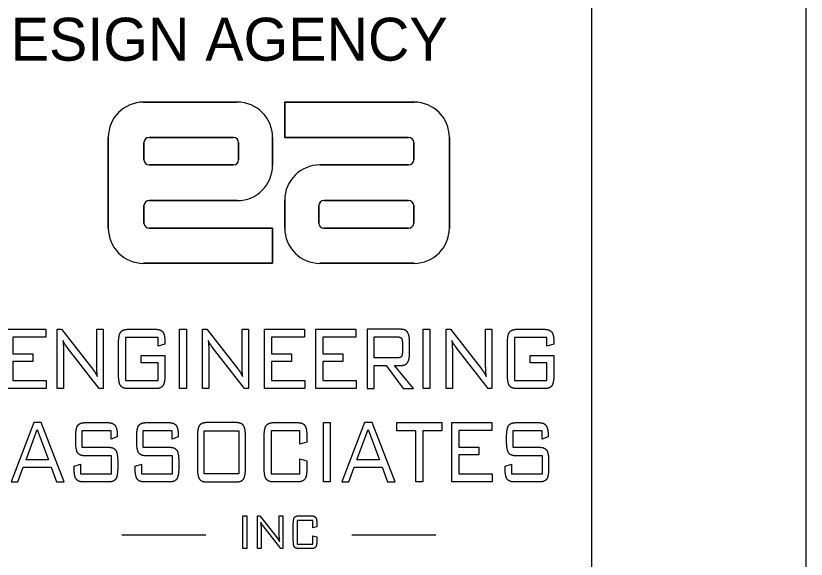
# Model space of a CAD drawing. Extents: x 0 to 34, y 0 to 22.
# Drawn here: x 32.158 to 34, y 3.688 to 4.955 of the extents above; entities that cross this region are included whole.
import ezdxf

# ---------------------------------------------------------------- set-up
doc = ezdxf.new("R2010")
doc.units = 0
for name, color, linetype in [('SH_Border', 7, 'Continuous'), ('SH_Cut_Line', 7, 'Continuous'), ('SH_Data', 7, 'Continuous'), ('TX_X_20', 7, 'Continuous')]:
    doc.layers.add(name, color=color, linetype=linetype)

msp = doc.modelspace()

# ---------------------------------------------------------------- linework, layer by layer
at = {"layer": 'SH_Border'}
msp.add_lwpolyline([(1.5, 21.5), (33.5, 21.5), (33.5, 0.5), (1.5, 0.5)], close=True, dxfattribs=at)
at = {"layer": 'SH_Cut_Line'}
msp.add_lwpolyline([(0, 0), (34, 0), (34, 22), (0, 22)], close=True, dxfattribs=at)
at = {"layer": 'SH_Data'}
msp.add_line((32.75, 4), (32.75, 4), dxfattribs=at)
at = {"layer": 'TX_X_20'}
for p, q in [((32.6745, 4.7533), (32.456, 4.7533)), ((32.456, 4.7533), (32.6745, 4.7533)), ((32.785, 4.7533), (33.0865, 4.7533)), ((32.785, 4.6713), (32.785, 4.7533)), ((32.3739, 4.6713), (32.3739, 4.4597)), ((32.3739, 4.4597), (32.3739, 4.6713)), ((32.457, 4.6189), (32.457, 4.6594)), ((32.457, 4.6594), (32.457, 4.6189)), ((32.4688, 4.6713), (32.6656, 4.6713)), ((32.6656, 4.6713), (32.4688, 4.6713)), ((32.6775, 4.6594), (32.6775, 4.6189)), ((32.6775, 4.6189), (32.6775, 4.6594)), ((32.7566, 4.606), (32.7566, 4.6713)), ((32.7566, 4.6713), (32.7566, 4.606)), ((33.0737, 4.6713), (32.785, 4.6713)), ((33.0855, 4.6594), (33.0855, 4.6189)), ((33.0855, 4.6189), (33.0855, 4.6594)), ((33.1686, 4.4597), (33.1686, 4.6713)), ((33.1686, 4.6713), (33.1686, 4.4597)), ((32.6656, 4.607), (32.4688, 4.607)), ((32.4688, 4.607), (32.6656, 4.607)), ((33.0737, 4.607), (32.8671, 4.607)), ((32.8671, 4.607), (33.0737, 4.607)), ((32.457, 4.4716), (32.457, 4.5121)), ((32.457, 4.5121), (32.457, 4.4716)), ((32.4688, 4.524), (32.6745, 4.524)), ((32.6745, 4.524), (32.4688, 4.524)), ((32.785, 4.525), (32.785, 4.4597)), ((32.785, 4.4597), (32.785, 4.525)), ((32.8641, 4.4716), (32.8641, 4.5121)), ((32.8641, 4.5121), (32.8641, 4.4716)), ((32.876, 4.524), (33.0737, 4.524)), ((33.0737, 4.524), (32.876, 4.524)), ((33.0855, 4.5121), (33.0855, 4.4716)), ((33.0855, 4.4716), (33.0855, 4.5121)), ((32.4688, 4.4597), (32.7566, 4.4597)), ((32.7566, 4.4597), (32.7566, 4.3777)), ((33.0737, 4.4597), (32.876, 4.4597)), ((32.876, 4.4597), (33.0737, 4.4597)), ((32.7566, 4.3777), (32.456, 4.3777)), ((32.8671, 4.3777), (33.0865, 4.3777)), ((33.0865, 4.3777), (32.8671, 4.3777)), ((32.4205, 4.224), (32.4832, 4.224)), ((33.3267, 4.224), (33.3893, 4.224)), ((32.3978, 4.1184), (32.3978, 4.1913)), ((33.0591, 4.1918), (33.0591, 4.1716)), ((33.0755, 4.1662), (33.0755, 4.1972)), ((33.3039, 4.1184), (33.3039, 4.1913)), ((32.4832, 4.0856), (32.4205, 4.0856)), ((33.3893, 4.0856), (33.3267, 4.0856)), ((32.3205, 4.0065), (32.3719, 4.0065)), ((32.4627, 4.0065), (32.5142, 4.0065)), ((32.6711, 4.0065), (32.6041, 4.0065)), ((32.7599, 4.0065), (32.814, 4.0065)), ((33.3246, 4.0065), (33.3761, 4.0065)), ((32.2979, 3.9618), (32.2979, 3.9738)), ((32.4401, 3.9618), (32.4401, 3.9738)), ((32.5814, 3.9738), (32.5814, 3.9009)), ((32.6936, 3.9009), (32.6936, 3.9738)), ((32.7371, 3.9009), (32.7371, 3.9738)), ((33.302, 3.9618), (33.302, 3.9738)), ((32.3958, 3.9164), (32.3958, 3.9009)), ((32.538, 3.9164), (32.538, 3.9009)), ((33.3999, 3.9164), (33.3999, 3.9009)), ((32.3733, 3.8681), (32.3169, 3.8681)), ((32.5155, 3.8681), (32.4591, 3.8681)), ((32.6041, 3.8681), (32.6711, 3.8681)), ((32.814, 3.8681), (32.7599, 3.8681)), ((33.3774, 3.8681), (33.321, 3.8681)), ((32.8175, 3.7891), (32.8473, 3.7891)), ((32.805, 3.7309), (32.805, 3.7711)), ((32.4056, 3.7451), (32.6008, 3.7451)), ((32.9416, 3.7451), (33.1369, 3.7451)), ((32.8473, 3.7129), (32.8175, 3.7129))]:
    msp.add_line(p, q, dxfattribs=at)
for points in [[(33.0865, 4.7533), (32.785, 4.7533), (32.785, 4.6713), (33.0737, 4.6713)], [(32.456, 4.3777), (32.7566, 4.3777), (32.7566, 4.4597), (32.4688, 4.4597)], [(32.2695, 4.1672), (32.2695, 4.0856), (32.2547, 4.0856), (32.2547, 4.224), (32.2649, 4.224), (32.3374, 4.1315)], [(32.3469, 4.1481), (32.3469, 4.224), (32.3617, 4.224), (32.3617, 4.0856), (32.3526, 4.0856), (32.2782, 4.1819)], [(32.608, 4.1672), (32.608, 4.0856), (32.5932, 4.0856), (32.5932, 4.224), (32.6034, 4.224), (32.6759, 4.1315)], [(32.6854, 4.1481), (32.6854, 4.224), (32.7002, 4.224), (32.7002, 4.0856), (32.6912, 4.0856), (32.6168, 4.1819)], [(33.055, 4.224), (32.9769, 4.224), (32.9769, 4.0856), (32.9932, 4.0856), (32.9932, 4.1395), (33.0217, 4.1395), (33.0611, 4.0856), (33.0851, 4.0856), (33.0408, 4.1395), (33.055, 4.1395)], [(33.1756, 4.1672), (33.1756, 4.0856), (33.1608, 4.0856), (33.1608, 4.224), (33.171, 4.224), (33.2435, 4.1315)], [(33.253, 4.1481), (33.253, 4.224), (33.2678, 4.224), (33.2678, 4.0856), (33.2588, 4.0856), (33.1844, 4.1819)], [(32.5059, 4.1929), (32.5059, 4.1895), (32.4898, 4.1849), (32.4898, 4.2052), (32.4139, 4.2052), (32.4139, 4.1049), (32.4898, 4.1049), (32.4898, 4.1456), (32.4506, 4.1456), (32.4506, 4.1632), (32.5059, 4.1632), (32.5059, 4.1184)], [(33.0487, 4.1574), (32.9932, 4.1574), (32.9932, 4.2062), (33.0487, 4.2062)], [(33.4121, 4.1929), (33.4121, 4.1895), (33.3959, 4.1849), (33.3959, 4.2052), (33.3201, 4.2052), (33.3201, 4.1049), (33.3959, 4.1049), (33.3959, 4.1456), (33.3567, 4.1456), (33.3567, 4.1632), (33.4121, 4.1632), (33.4121, 4.1184)], [(32.3947, 3.9762), (32.3947, 3.9733), (32.3808, 3.9676), (32.3808, 3.9877), (32.3124, 3.9877), (32.3124, 3.9491), (32.3733, 3.9491)], [(32.5369, 3.9762), (32.5369, 3.9733), (32.523, 3.9676), (32.523, 3.9877), (32.4546, 3.9877), (32.4546, 3.9491), (32.5155, 3.9491)], [(32.8366, 3.9738), (32.8366, 3.9608), (32.8204, 3.9565), (32.8204, 3.9877), (32.7533, 3.9877), (32.7533, 3.8874), (32.8204, 3.8874), (32.8204, 3.9221), (32.8366, 3.9172), (32.8366, 3.9009)], [(33.3988, 3.9762), (33.3988, 3.9733), (33.3849, 3.9676), (33.3849, 3.9877), (33.3165, 3.9877), (33.3165, 3.9491), (33.3774, 3.9491)], [(32.2942, 3.9009), (32.2942, 3.9047), (32.3092, 3.9096), (32.3092, 3.8874), (32.3813, 3.8874), (32.3813, 3.929), (32.3205, 3.929)], [(32.4364, 3.9009), (32.4364, 3.9047), (32.4514, 3.9096), (32.4514, 3.8874), (32.5235, 3.8874), (32.5235, 3.929), (32.4627, 3.929)], [(33.2983, 3.9009), (33.2983, 3.9047), (33.3133, 3.9096), (33.3133, 3.8874), (33.3854, 3.8874), (33.3854, 3.929), (33.3246, 3.929)], [(32.7298, 3.7578), (32.7298, 3.7129), (32.7216, 3.7129), (32.7216, 3.7891), (32.7272, 3.7891), (32.7671, 3.7381)], [(32.7723, 3.7473), (32.7723, 3.7891), (32.7805, 3.7891), (32.7805, 3.7129), (32.7755, 3.7129), (32.7345, 3.7659)], [(32.8597, 3.7711), (32.8597, 3.7639), (32.8507, 3.7615), (32.8507, 3.7787), (32.8139, 3.7787), (32.8139, 3.7235), (32.8507, 3.7235), (32.8507, 3.7426), (32.8597, 3.7399), (32.8597, 3.7309)]]:
    msp.add_lwpolyline(points, dxfattribs=at)
for points in [[(32.1351, 4.0856), (32.1351, 4.224), (32.2283, 4.224), (32.2283, 4.2055), (32.1513, 4.2055), (32.1513, 4.167), (32.1984, 4.167), (32.1984, 4.1487), (32.1513, 4.1487), (32.1513, 4.1046), (32.2291, 4.1046), (32.2291, 4.0856)], [(32.5396, 4.0856), (32.5396, 4.224), (32.5558, 4.224), (32.5558, 4.0856)], [(32.7376, 4.0856), (32.7376, 4.224), (32.8309, 4.224), (32.8309, 4.2055), (32.7539, 4.2055), (32.7539, 4.167), (32.801, 4.167), (32.801, 4.1487), (32.7539, 4.1487), (32.7539, 4.1046), (32.8316, 4.1046), (32.8316, 4.0856)], [(32.8573, 4.0856), (32.8573, 4.224), (32.9505, 4.224), (32.9505, 4.2055), (32.8735, 4.2055), (32.8735, 4.167), (32.9206, 4.167), (32.9206, 4.1487), (32.8735, 4.1487), (32.8735, 4.1046), (32.9513, 4.1046), (32.9513, 4.0856)], [(33.1072, 4.0856), (33.1072, 4.224), (33.1234, 4.224), (33.1234, 4.0856)], [(32.1472, 3.8681), (32.1631, 3.8681), (32.1755, 3.9023), (32.241, 3.9023), (32.2534, 3.8681), (32.2712, 3.8681), (32.2174, 4.0065), (32.2001, 4.0065)], [(32.875, 3.8681), (32.875, 4.0065), (32.8912, 4.0065), (32.8912, 3.8681)], [(32.9182, 3.8681), (32.9341, 3.8681), (32.9465, 3.9023), (33.012, 3.9023), (33.0244, 3.8681), (33.0422, 3.8681), (32.9884, 4.0065), (32.9711, 4.0065)], [(33.1068, 3.9877), (33.1068, 3.8681), (33.0907, 3.8681), (33.0907, 3.9877), (33.0464, 3.9877), (33.0464, 4.0065), (33.1513, 4.0065), (33.1513, 3.9877)], [(33.1742, 3.8681), (33.1742, 4.0065), (33.2675, 4.0065), (33.2675, 3.988), (33.1905, 3.988), (33.1905, 3.9495), (33.2376, 3.9495), (33.2376, 3.9312), (33.1905, 3.9312), (33.1905, 3.8871), (33.2682, 3.8871), (33.2682, 3.8681)], [(32.1823, 3.9199), (32.2083, 3.9907), (32.2344, 3.9199)], [(32.5975, 3.8874), (32.5975, 3.9877), (32.6777, 3.9877), (32.6777, 3.8874)], [(32.9533, 3.9199), (32.9793, 3.9907), (33.0054, 3.9199)], [(32.6874, 3.7129), (32.6874, 3.7891), (32.6964, 3.7891), (32.6964, 3.7129)]]:
    msp.add_lwpolyline(points, close=True, dxfattribs=at)
for centre, radius, start, end in [((32.456, 4.6713), 0.0821, 90, 180), ((32.456, 4.6713), 0.0821, 90, 180), ((32.6745, 4.6713), 0.0821, 0, 90), ((32.6745, 4.6713), 0.0821, 0, 90), ((33.0865, 4.6713), 0.0821, 0, 90), ((33.0865, 4.6713), 0.0821, 0, 90), ((32.4688, 4.6594), 0.0119, 90, 180), ((32.4688, 4.6594), 0.0119, 90, 180), ((32.6656, 4.6594), 0.0119, 0, 90), ((32.6656, 4.6594), 0.0119, 0, 90), ((33.0737, 4.6594), 0.0119, 0, 90), ((33.0737, 4.6594), 0.0119, 0, 90), ((32.4688, 4.6189), 0.0119, 180, 270), ((32.4688, 4.6189), 0.0119, 180, 270), ((32.6656, 4.6189), 0.0119, 270, 0), ((32.6656, 4.6189), 0.0119, 270, 0), ((32.6745, 4.606), 0.0821, 270, 360), ((32.6745, 4.606), 0.0821, 270, 360), ((32.8671, 4.525), 0.0821, 90, 180), ((32.8671, 4.525), 0.0821, 90, 180), ((33.0737, 4.6189), 0.0119, 270, 0), ((33.0737, 4.6189), 0.0119, 270, 0), ((32.4688, 4.5121), 0.0119, 90, 180), ((32.4688, 4.5121), 0.0119, 90, 180), ((32.876, 4.5121), 0.0119, 90, 180), ((32.876, 4.5121), 0.0119, 90, 180), ((33.0737, 4.5121), 0.0119, 0, 90), ((33.0737, 4.5121), 0.0119, 0, 90), ((32.456, 4.4597), 0.0821, 180, 270), ((32.456, 4.4597), 0.0821, 180, 270), ((32.4688, 4.4716), 0.0119, 180, 270), ((32.4688, 4.4716), 0.0119, 180, 270), ((32.8671, 4.4597), 0.0821, 180, 270), ((32.8671, 4.4597), 0.0821, 180, 270), ((32.876, 4.4716), 0.0119, 180, 270), ((32.876, 4.4716), 0.0119, 180, 270), ((33.0737, 4.4716), 0.0119, 270, 0), ((33.0737, 4.4716), 0.0119, 270, 0), ((33.0865, 4.4597), 0.0821, 270, 360), ((33.0865, 4.4597), 0.0821, 270, 360)]:
    msp.add_arc(centre, radius, start, end, dxfattribs=at)
for points in [[(32.4025, 4.2171), (32.4072, 4.224), (32.4205, 4.224)], [(32.4832, 4.224), (32.4962, 4.224), (32.5011, 4.2173)], [(33.0707, 4.2177), (33.0659, 4.224), (33.055, 4.224)], [(33.0755, 4.1972), (33.0755, 4.2113), (33.0707, 4.2177)], [(33.3086, 4.2171), (33.3134, 4.224), (33.3267, 4.224)], [(33.3893, 4.224), (33.4023, 4.224), (33.4072, 4.2173)], [(32.3978, 4.1913), (32.3978, 4.2102), (32.4025, 4.2171)], [(32.5011, 4.2173), (32.5059, 4.2105), (32.5059, 4.1929)], [(33.0487, 4.2062), (33.0546, 4.2062), (33.0569, 4.2029)], [(33.0569, 4.2029), (33.0591, 4.1997), (33.0591, 4.1918)], [(33.3039, 4.1913), (33.3039, 4.2102), (33.3086, 4.2171)], [(33.4072, 4.2173), (33.4121, 4.2105), (33.4121, 4.1929)], [(32.2766, 4.184), (32.2711, 4.191), (32.2684, 4.1975)], [(32.2684, 4.1975), (32.269, 4.1912), (32.2692, 4.184)], [(32.2692, 4.184), (32.2695, 4.1769), (32.2695, 4.1672)], [(32.2782, 4.1819), (32.2777, 4.1825), (32.2766, 4.184)], [(32.6151, 4.184), (32.6096, 4.191), (32.6069, 4.1975)], [(32.6069, 4.1975), (32.6075, 4.1912), (32.6078, 4.184)], [(32.6078, 4.184), (32.608, 4.1769), (32.608, 4.1672)], [(32.6168, 4.1819), (32.6162, 4.1825), (32.6151, 4.184)], [(33.1827, 4.184), (33.1772, 4.191), (33.1746, 4.1975)], [(33.1746, 4.1975), (33.1751, 4.1912), (33.1754, 4.184)], [(33.1754, 4.184), (33.1756, 4.1769), (33.1756, 4.1672)], [(33.1844, 4.1819), (33.1838, 4.1825), (33.1827, 4.184)], [(33.0591, 4.1716), (33.0591, 4.1637), (33.0569, 4.1606)], [(33.0707, 4.1459), (33.0755, 4.1522), (33.0755, 4.1662)], [(32.3473, 4.128), (32.3469, 4.1353), (32.3469, 4.1481)], [(32.6858, 4.128), (32.6854, 4.1353), (32.6854, 4.1481)], [(33.0569, 4.1606), (33.0547, 4.1574), (33.0487, 4.1574)], [(33.055, 4.1395), (33.0659, 4.1395), (33.0707, 4.1459)], [(33.2534, 4.128), (33.253, 4.1353), (33.253, 4.1481)], [(32.3374, 4.1315), (32.3398, 4.1283), (32.3426, 4.1239)], [(32.3484, 4.114), (32.3476, 4.1207), (32.3473, 4.128)], [(32.6759, 4.1315), (32.6784, 4.1283), (32.6812, 4.1239)], [(32.6869, 4.114), (32.6862, 4.1207), (32.6858, 4.128)], [(33.2435, 4.1315), (33.246, 4.1283), (33.2488, 4.1239)], [(33.2545, 4.114), (33.2538, 4.1207), (33.2534, 4.128)], [(32.3426, 4.1239), (32.3454, 4.1194), (32.3484, 4.114)], [(32.4025, 4.0926), (32.3978, 4.0995), (32.3978, 4.1184)], [(32.5059, 4.1184), (32.5059, 4.0994), (32.5012, 4.0925)], [(32.6812, 4.1239), (32.684, 4.1194), (32.6869, 4.114)], [(33.2488, 4.1239), (33.2516, 4.1194), (33.2545, 4.114)], [(33.3086, 4.0926), (33.3039, 4.0995), (33.3039, 4.1184)], [(33.4121, 4.1184), (33.4121, 4.0994), (33.4073, 4.0925)], [(32.4205, 4.0856), (32.4072, 4.0856), (32.4025, 4.0926)], [(32.5012, 4.0925), (32.4964, 4.0856), (32.4832, 4.0856)], [(33.3267, 4.0856), (33.3134, 4.0856), (33.3086, 4.0926)], [(33.4073, 4.0925), (33.4025, 4.0856), (33.3893, 4.0856)], [(32.2979, 3.9738), (32.2979, 3.9928), (32.3026, 3.9997)], [(32.3026, 3.9997), (32.3072, 4.0065), (32.3205, 4.0065)], [(32.3719, 4.0065), (32.3849, 4.0065), (32.3898, 3.9998)], [(32.3898, 3.9998), (32.3947, 3.9931), (32.3947, 3.9762)], [(32.4401, 3.9738), (32.4401, 3.9928), (32.4448, 3.9997)], [(32.4448, 3.9997), (32.4495, 4.0065), (32.4627, 4.0065)], [(32.5142, 4.0065), (32.5271, 4.0065), (32.532, 3.9998)], [(32.532, 3.9998), (32.5369, 3.9931), (32.5369, 3.9762)], [(32.5861, 3.9996), (32.5814, 3.9927), (32.5814, 3.9738)], [(32.6041, 4.0065), (32.5908, 4.0065), (32.5861, 3.9996)], [(32.6889, 3.9997), (32.6842, 4.0065), (32.6711, 4.0065)], [(32.6936, 3.9738), (32.6936, 3.9928), (32.6889, 3.9997)], [(32.7371, 3.9738), (32.7371, 3.9928), (32.7419, 3.9997)], [(32.7419, 3.9997), (32.7467, 4.0065), (32.7599, 4.0065)], [(32.814, 4.0065), (32.8272, 4.0065), (32.8319, 3.9997)], [(32.8319, 3.9997), (32.8366, 3.9929), (32.8366, 3.9738)], [(33.302, 3.9738), (33.302, 3.9928), (33.3067, 3.9997)], [(33.3067, 3.9997), (33.3114, 4.0065), (33.3246, 4.0065)], [(33.3761, 4.0065), (33.389, 4.0065), (33.3939, 3.9998)], [(33.3939, 3.9998), (33.3988, 3.9931), (33.3988, 3.9762)], [(32.3026, 3.9359), (32.2979, 3.9428), (32.2979, 3.9618)], [(32.4448, 3.9359), (32.4401, 3.9428), (32.4401, 3.9618)], [(33.3067, 3.9359), (33.302, 3.9428), (33.302, 3.9618)], [(32.3733, 3.9491), (32.3863, 3.9491), (32.391, 3.9423)], [(32.391, 3.9423), (32.3958, 3.9355), (32.3958, 3.9164)], [(32.5155, 3.9491), (32.5285, 3.9491), (32.5333, 3.9423)], [(32.5333, 3.9423), (32.538, 3.9355), (32.538, 3.9164)], [(33.3774, 3.9491), (33.3904, 3.9491), (33.3952, 3.9423)], [(33.3952, 3.9423), (33.3999, 3.9355), (33.3999, 3.9164)], [(32.3205, 3.929), (32.3072, 3.929), (32.3026, 3.9359)], [(32.4627, 3.929), (32.4495, 3.929), (32.4448, 3.9359)], [(33.3246, 3.929), (33.3114, 3.929), (33.3067, 3.9359)], [(32.2989, 3.875), (32.2942, 3.8819), (32.2942, 3.9009)], [(32.3958, 3.9009), (32.3958, 3.8818), (32.3911, 3.875)], [(32.4411, 3.875), (32.4364, 3.8819), (32.4364, 3.9009)], [(32.538, 3.9009), (32.538, 3.8818), (32.5333, 3.875)], [(32.5814, 3.9009), (32.5814, 3.882), (32.5861, 3.8751)], [(32.6889, 3.875), (32.6936, 3.8818), (32.6936, 3.9009)], [(32.7419, 3.875), (32.7371, 3.8819), (32.7371, 3.9009)], [(32.8366, 3.9009), (32.8366, 3.8818), (32.8319, 3.875)], [(33.3031, 3.875), (33.2983, 3.8819), (33.2983, 3.9009)], [(33.3999, 3.9009), (33.3999, 3.8818), (33.3953, 3.875)], [(32.3169, 3.8681), (32.3037, 3.8681), (32.2989, 3.875)], [(32.3911, 3.875), (32.3865, 3.8681), (32.3733, 3.8681)], [(32.4591, 3.8681), (32.4459, 3.8681), (32.4411, 3.875)], [(32.5333, 3.875), (32.5287, 3.8681), (32.5155, 3.8681)], [(32.5861, 3.8751), (32.5908, 3.8681), (32.6041, 3.8681)], [(32.6711, 3.8681), (32.6842, 3.8681), (32.6889, 3.875)], [(32.7599, 3.8681), (32.7467, 3.8681), (32.7419, 3.875)], [(32.8319, 3.875), (32.8272, 3.8681), (32.814, 3.8681)], [(33.321, 3.8681), (33.3078, 3.8681), (33.3031, 3.875)], [(33.3953, 3.875), (33.3906, 3.8681), (33.3774, 3.8681)], [(32.805, 3.7711), (32.805, 3.7815), (32.8076, 3.7853)], [(32.8076, 3.7853), (32.8102, 3.7891), (32.8175, 3.7891)], [(32.8473, 3.7891), (32.8545, 3.7891), (32.8571, 3.7853)], [(32.8571, 3.7853), (32.8597, 3.7816), (32.8597, 3.7711)], [(32.7336, 3.767), (32.7306, 3.7709), (32.7292, 3.7744)], [(32.7292, 3.7744), (32.7295, 3.771), (32.7296, 3.7671)], [(32.7296, 3.7671), (32.7298, 3.7631), (32.7298, 3.7578)], [(32.7345, 3.7659), (32.7342, 3.7662), (32.7336, 3.767)], [(32.7725, 3.7362), (32.7723, 3.7402), (32.7723, 3.7473)], [(32.7671, 3.7381), (32.7684, 3.7364), (32.77, 3.734)], [(32.77, 3.734), (32.7715, 3.7315), (32.7731, 3.7286)], [(32.7731, 3.7286), (32.7727, 3.7322), (32.7725, 3.7362)], [(32.8076, 3.7167), (32.805, 3.7205), (32.805, 3.7309)], [(32.8597, 3.7309), (32.8597, 3.7204), (32.8571, 3.7167)], [(32.8175, 3.7129), (32.8102, 3.7129), (32.8076, 3.7167)], [(32.8571, 3.7167), (32.8545, 3.7129), (32.8473, 3.7129)]]:
    msp.add_open_spline(points, degree=2, dxfattribs=at)

# ---------------------------------------------------------------- texts
at = {"layer": 'SH_Data'}
msp.add_text('DESIGN AGENCY', height=0.1, dxfattribs=at).set_placement((32.05, 4.85))

doc.saveas('drawing.dxf')
